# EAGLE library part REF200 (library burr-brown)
Dual Current Source/Current Sink
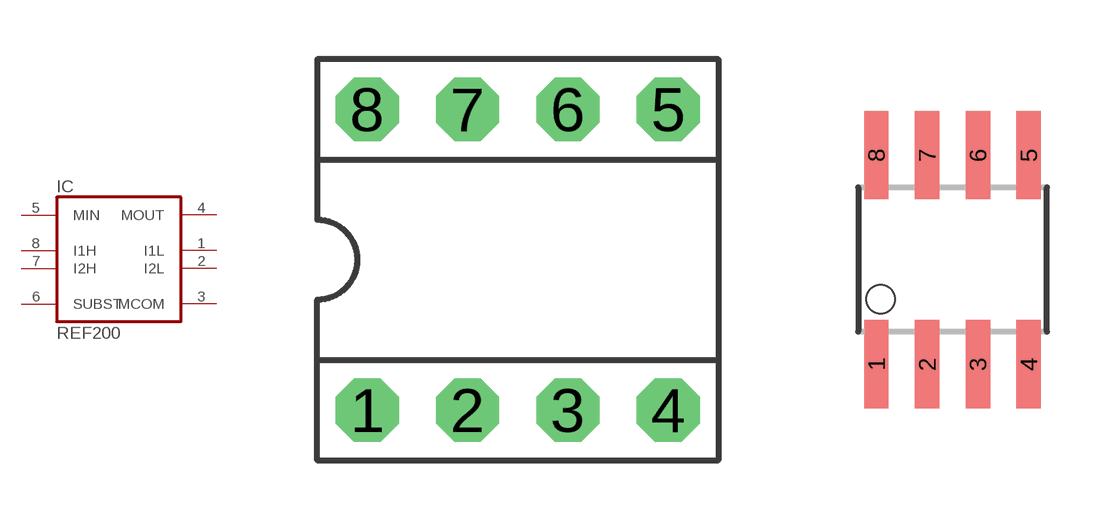
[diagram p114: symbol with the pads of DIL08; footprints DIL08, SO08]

Designator prefix IC

## REF200P (OC_FARNELL: unknown; OC_NEWARK: unknown)  [DIL08]
1  I1L  pas
2  I2L  pas
3  MCOM  pas
4  MOUT  out
5  MIN  in
6  SUBST  pas
7  I2H  pas
8  I1H  pas

## REF200U (MF: TEXAS INSTRUMENTS; MPN: REF200AU; OC_FARNELL: 1207240; OC_NEWARK: 34C7615)  [SO08]
Pads as for DIL08

## Footprint DIL08 (pad centres in mm)
Dual In Line
drill 0.813 pad 1.6 octagon: 1 -3.81,-3.81; 2 -1.27,-3.81; 3 1.27,-3.81; 4 3.81,-3.81; 5 3.81,3.81; 6 1.27,3.81; 7 -1.27,3.81; 8 -3.81,3.81

## Footprint SO08 (pad centres in mm)
Small Outline Package
smd 0.61 x 2.21: 1 -1.905,-2.616; 2 -0.635,-2.616; 3 0.635,-2.616; 4 1.905,-2.616; 5 1.905,2.616; 6 0.635,2.616; 7 -0.635,2.616; 8 -1.905,2.616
